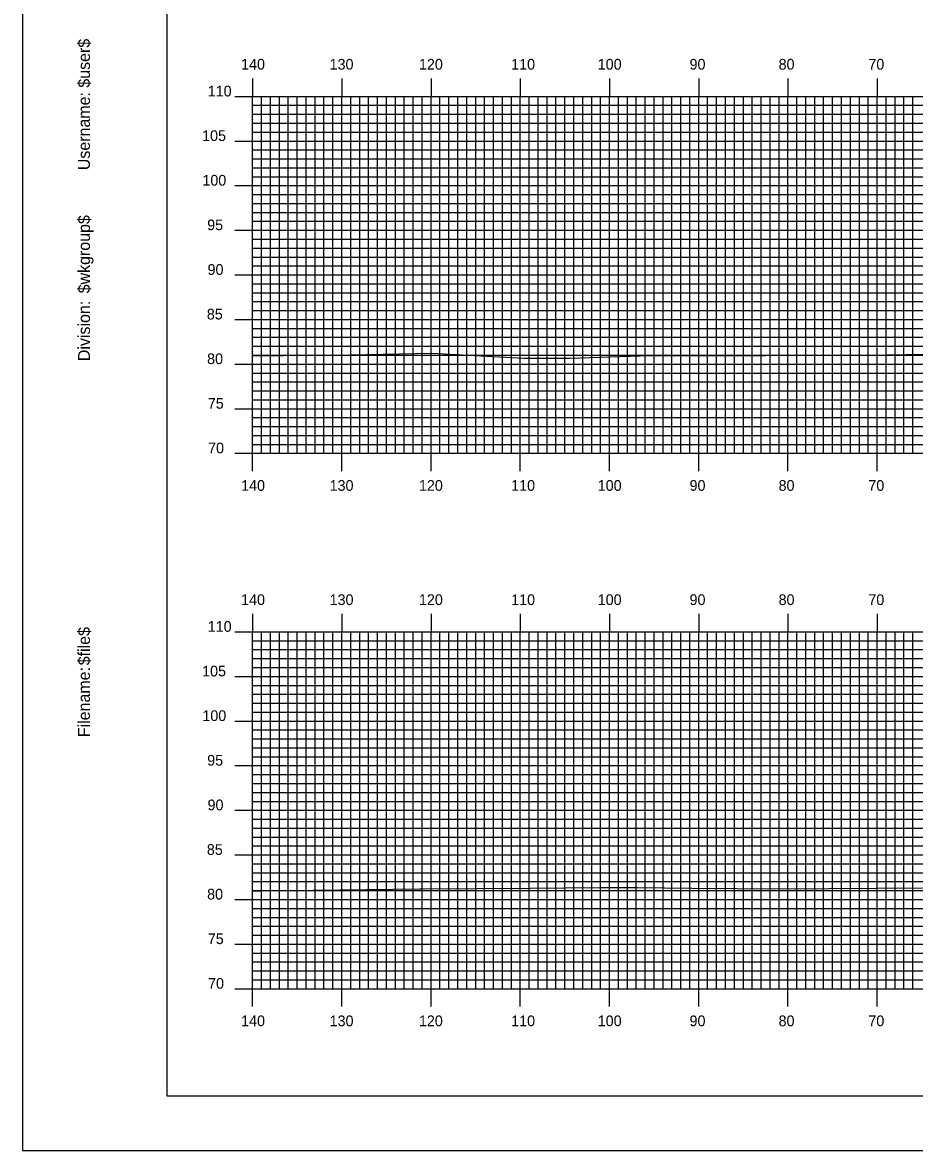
# Model space of a CAD drawing. Extents: x 1759036 to 1759380, y 442591 to 442811.
# Drawn here: x 1759036.4 to 1759136.3, y 442590.5 to 442716.9 of the extents above; entities that cross this region are included whole.
import ezdxf

# ---------------------------------------------------------------- set-up
doc = ezdxf.new("R2010")
doc.units = 0
for name, color, linetype in [('BORDER', 7, 'Continuous'), ('H_V ANNOTATION', 7, 'Continuous'), ('MAJOR', 7, 'Continuous'), ('MINOR', 7, 'Continuous'), ('PLOT BOUNDARY', 7, 'Continuous'), ('S_Roadway_Centerline', 7, 'Continuous')]:
    doc.layers.add(name, color=color, linetype=linetype)

msp = doc.modelspace()

# ---------------------------------------------------------------- linework, layer by layer
at = {"layer": 'BORDER'}
msp.add_lwpolyline([(1759052.56, 442596.67), (1759372.56, 442596.67), (1759372.56, 442806.67), (1759052.56, 442806.67)], close=True, dxfattribs=at)
at = {"layer": 'MAJOR'}
for p, q in [((1759062.16, 442710.67), (1759062.16, 442708.67)), ((1759072.16, 442710.67), (1759072.16, 442708.67)), ((1759082.16, 442710.67), (1759082.16, 442708.67)), ((1759092.16, 442710.67), (1759092.16, 442708.67)), ((1759102.16, 442710.67), (1759102.16, 442708.67)), ((1759112.16, 442710.67), (1759112.16, 442708.67)), ((1759122.16, 442710.67), (1759122.16, 442708.67)), ((1759132.16, 442710.67), (1759132.16, 442708.67)), ((1759060.16, 442708.67), (1759062.16, 442708.67)), ((1759062.16, 442708.67), (1759342.16, 442708.67)), ((1759062.16, 442668.67), (1759062.16, 442708.67)), ((1759062.16, 442668.67), (1759062.16, 442708.67)), ((1759062.16, 442708.67), (1759342.16, 442708.67)), ((1759072.16, 442668.67), (1759072.16, 442708.67)), ((1759082.16, 442668.67), (1759082.16, 442708.67)), ((1759092.16, 442668.67), (1759092.16, 442708.67)), ((1759102.16, 442668.67), (1759102.16, 442708.67)), ((1759112.16, 442668.67), (1759112.16, 442708.67)), ((1759122.16, 442668.67), (1759122.16, 442708.67)), ((1759132.16, 442668.67), (1759132.16, 442708.67)), ((1759060.16, 442703.67), (1759062.16, 442703.67)), ((1759062.16, 442703.67), (1759342.16, 442703.67)), ((1759060.16, 442698.67), (1759062.16, 442698.67)), ((1759062.16, 442698.67), (1759342.16, 442698.67)), ((1759060.16, 442693.67), (1759062.16, 442693.67)), ((1759062.16, 442693.67), (1759342.16, 442693.67)), ((1759060.16, 442688.67), (1759062.16, 442688.67)), ((1759062.16, 442688.67), (1759342.16, 442688.67)), ((1759060.16, 442683.67), (1759062.16, 442683.67)), ((1759062.16, 442683.67), (1759342.16, 442683.67)), ((1759060.16, 442678.67), (1759062.16, 442678.67)), ((1759062.16, 442678.67), (1759342.16, 442678.67)), ((1759060.16, 442673.67), (1759062.16, 442673.67)), ((1759062.16, 442673.67), (1759342.16, 442673.67)), ((1759060.16, 442668.67), (1759062.16, 442668.67)), ((1759062.16, 442668.67), (1759342.16, 442668.67)), ((1759062.16, 442668.67), (1759342.16, 442668.67)), ((1759062.16, 442666.66), (1759062.16, 442668.67)), ((1759072.16, 442666.66), (1759072.16, 442668.67)), ((1759082.16, 442666.66), (1759082.16, 442668.67)), ((1759092.16, 442666.66), (1759092.16, 442668.67)), ((1759102.16, 442666.66), (1759102.16, 442668.67)), ((1759112.16, 442666.66), (1759112.16, 442668.67)), ((1759122.16, 442666.66), (1759122.16, 442668.67)), ((1759132.16, 442666.66), (1759132.16, 442668.67)), ((1759062.16, 442650.67), (1759062.16, 442648.67)), ((1759072.16, 442650.67), (1759072.16, 442648.67)), ((1759082.16, 442650.67), (1759082.16, 442648.67)), ((1759092.16, 442650.67), (1759092.16, 442648.67)), ((1759102.16, 442650.67), (1759102.16, 442648.67)), ((1759112.16, 442650.67), (1759112.16, 442648.67)), ((1759122.16, 442650.67), (1759122.16, 442648.67)), ((1759132.16, 442650.67), (1759132.16, 442648.67)), ((1759060.16, 442648.67), (1759062.16, 442648.67)), ((1759062.16, 442648.67), (1759342.16, 442648.67)), ((1759062.16, 442608.67), (1759062.16, 442648.67)), ((1759062.16, 442608.67), (1759062.16, 442648.67)), ((1759062.16, 442648.67), (1759342.16, 442648.67)), ((1759072.16, 442608.67), (1759072.16, 442648.67)), ((1759082.16, 442608.67), (1759082.16, 442648.67)), ((1759092.16, 442608.67), (1759092.16, 442648.67)), ((1759102.16, 442608.67), (1759102.16, 442648.67)), ((1759112.16, 442608.67), (1759112.16, 442648.67)), ((1759122.16, 442608.67), (1759122.16, 442648.67)), ((1759132.16, 442608.67), (1759132.16, 442648.67)), ((1759060.16, 442643.67), (1759062.16, 442643.67)), ((1759062.16, 442643.67), (1759342.16, 442643.67)), ((1759060.16, 442638.67), (1759062.16, 442638.67)), ((1759062.16, 442638.67), (1759342.16, 442638.67)), ((1759060.16, 442633.67), (1759062.16, 442633.67)), ((1759062.16, 442633.67), (1759342.16, 442633.67)), ((1759060.16, 442628.67), (1759062.16, 442628.67)), ((1759062.16, 442628.67), (1759342.16, 442628.67)), ((1759060.16, 442623.67), (1759062.16, 442623.67)), ((1759062.16, 442623.67), (1759342.16, 442623.67)), ((1759060.16, 442618.67), (1759062.16, 442618.67)), ((1759062.16, 442618.67), (1759342.16, 442618.67)), ((1759060.16, 442613.67), (1759062.16, 442613.67)), ((1759062.16, 442613.67), (1759342.16, 442613.67)), ((1759060.16, 442608.67), (1759062.16, 442608.67)), ((1759062.16, 442608.67), (1759342.16, 442608.67)), ((1759062.16, 442608.67), (1759342.16, 442608.67)), ((1759062.16, 442606.66), (1759062.16, 442608.67)), ((1759072.16, 442606.66), (1759072.16, 442608.67)), ((1759082.16, 442606.66), (1759082.16, 442608.67)), ((1759092.16, 442606.66), (1759092.16, 442608.67)), ((1759102.16, 442606.66), (1759102.16, 442608.67)), ((1759112.16, 442606.66), (1759112.16, 442608.67)), ((1759122.16, 442606.66), (1759122.16, 442608.67)), ((1759132.16, 442606.66), (1759132.16, 442608.67))]:
    msp.add_line(p, q, dxfattribs=at)
at = {"layer": 'MINOR'}
for p, q in [((1759063.16, 442668.67), (1759063.16, 442708.67)), ((1759064.16, 442668.67), (1759064.16, 442708.67)), ((1759065.16, 442668.67), (1759065.16, 442708.67)), ((1759066.16, 442668.67), (1759066.16, 442708.67)), ((1759067.16, 442668.67), (1759067.16, 442708.67)), ((1759068.16, 442668.67), (1759068.16, 442708.67)), ((1759069.16, 442668.67), (1759069.16, 442708.67)), ((1759070.16, 442668.67), (1759070.16, 442708.67)), ((1759071.16, 442668.67), (1759071.16, 442708.67)), ((1759073.16, 442668.67), (1759073.16, 442708.67)), ((1759074.16, 442668.67), (1759074.16, 442708.67)), ((1759075.16, 442668.67), (1759075.16, 442708.67)), ((1759076.16, 442668.67), (1759076.16, 442708.67)), ((1759077.16, 442668.67), (1759077.16, 442708.67)), ((1759078.16, 442668.67), (1759078.16, 442708.67)), ((1759079.16, 442668.67), (1759079.16, 442708.67)), ((1759080.16, 442668.67), (1759080.16, 442708.67)), ((1759081.16, 442668.67), (1759081.16, 442708.67)), ((1759083.16, 442668.67), (1759083.16, 442708.67)), ((1759084.16, 442668.67), (1759084.16, 442708.67)), ((1759085.16, 442668.67), (1759085.16, 442708.67)), ((1759086.16, 442668.67), (1759086.16, 442708.67)), ((1759087.16, 442668.67), (1759087.16, 442708.67)), ((1759088.16, 442668.67), (1759088.16, 442708.67)), ((1759089.16, 442668.67), (1759089.16, 442708.67)), ((1759090.16, 442668.67), (1759090.16, 442708.67)), ((1759091.16, 442668.67), (1759091.16, 442708.67)), ((1759093.16, 442668.67), (1759093.16, 442708.67)), ((1759094.16, 442668.67), (1759094.16, 442708.67)), ((1759095.16, 442668.67), (1759095.16, 442708.67)), ((1759096.16, 442668.67), (1759096.16, 442708.67)), ((1759097.16, 442668.67), (1759097.16, 442708.67)), ((1759098.16, 442668.67), (1759098.16, 442708.67)), ((1759099.16, 442668.67), (1759099.16, 442708.67)), ((1759100.16, 442668.67), (1759100.16, 442708.67)), ((1759101.16, 442668.67), (1759101.16, 442708.67)), ((1759103.16, 442668.67), (1759103.16, 442708.67)), ((1759104.16, 442668.67), (1759104.16, 442708.67)), ((1759105.16, 442668.67), (1759105.16, 442708.67)), ((1759106.16, 442668.67), (1759106.16, 442708.67)), ((1759107.16, 442668.67), (1759107.16, 442708.67)), ((1759108.16, 442668.67), (1759108.16, 442708.67)), ((1759109.16, 442668.67), (1759109.16, 442708.67)), ((1759110.16, 442668.67), (1759110.16, 442708.67)), ((1759111.16, 442668.67), (1759111.16, 442708.67)), ((1759113.16, 442668.67), (1759113.16, 442708.67)), ((1759114.16, 442668.67), (1759114.16, 442708.67)), ((1759115.16, 442668.67), (1759115.16, 442708.67)), ((1759116.16, 442668.67), (1759116.16, 442708.67)), ((1759117.16, 442668.67), (1759117.16, 442708.67)), ((1759118.16, 442668.67), (1759118.16, 442708.67)), ((1759119.16, 442668.67), (1759119.16, 442708.67)), ((1759120.16, 442668.67), (1759120.16, 442708.67)), ((1759121.16, 442668.67), (1759121.16, 442708.67)), ((1759123.16, 442668.67), (1759123.16, 442708.67)), ((1759124.16, 442668.67), (1759124.16, 442708.67)), ((1759125.16, 442668.67), (1759125.16, 442708.67)), ((1759126.16, 442668.67), (1759126.16, 442708.67)), ((1759127.16, 442668.67), (1759127.16, 442708.67)), ((1759128.16, 442668.67), (1759128.16, 442708.67)), ((1759129.16, 442668.67), (1759129.16, 442708.67)), ((1759130.16, 442668.67), (1759130.16, 442708.67)), ((1759131.16, 442668.67), (1759131.16, 442708.67)), ((1759133.16, 442668.67), (1759133.16, 442708.67)), ((1759134.16, 442668.67), (1759134.16, 442708.67)), ((1759135.16, 442668.67), (1759135.16, 442708.67)), ((1759136.16, 442668.67), (1759136.16, 442708.67)), ((1759062.16, 442707.67), (1759342.16, 442707.67)), ((1759062.16, 442707.67), (1759064.17, 442707.67)), ((1759062.16, 442706.67), (1759342.16, 442706.67)), ((1759062.16, 442706.67), (1759064.17, 442706.67)), ((1759062.16, 442705.67), (1759342.16, 442705.67)), ((1759062.16, 442705.67), (1759064.17, 442705.67)), ((1759062.16, 442704.67), (1759342.16, 442704.67)), ((1759062.16, 442704.67), (1759064.17, 442704.67)), ((1759062.16, 442702.67), (1759342.16, 442702.67)), ((1759062.16, 442702.67), (1759064.17, 442702.67)), ((1759062.16, 442701.67), (1759342.16, 442701.67)), ((1759062.16, 442701.67), (1759064.17, 442701.67)), ((1759062.16, 442700.67), (1759342.16, 442700.67)), ((1759062.16, 442700.67), (1759064.17, 442700.67)), ((1759062.16, 442699.67), (1759342.16, 442699.67)), ((1759062.16, 442699.67), (1759064.17, 442699.67)), ((1759062.16, 442697.67), (1759342.16, 442697.67)), ((1759062.16, 442697.67), (1759064.17, 442697.67)), ((1759062.16, 442696.67), (1759342.16, 442696.67)), ((1759062.16, 442696.67), (1759064.17, 442696.67)), ((1759062.16, 442695.67), (1759342.16, 442695.67)), ((1759062.16, 442695.67), (1759064.17, 442695.67)), ((1759062.16, 442694.67), (1759342.16, 442694.67)), ((1759062.16, 442694.67), (1759064.17, 442694.67)), ((1759062.16, 442692.67), (1759342.16, 442692.67)), ((1759062.16, 442692.67), (1759064.17, 442692.67)), ((1759062.16, 442691.67), (1759342.16, 442691.67)), ((1759062.16, 442691.67), (1759064.17, 442691.67)), ((1759062.16, 442690.67), (1759342.16, 442690.67)), ((1759062.16, 442690.67), (1759064.17, 442690.67)), ((1759062.16, 442689.67), (1759342.16, 442689.67)), ((1759062.16, 442689.67), (1759064.17, 442689.67)), ((1759062.16, 442687.67), (1759342.16, 442687.67)), ((1759062.16, 442687.67), (1759064.17, 442687.67)), ((1759062.16, 442686.67), (1759342.16, 442686.67)), ((1759062.16, 442686.67), (1759064.17, 442686.67)), ((1759062.16, 442685.67), (1759342.16, 442685.67)), ((1759062.16, 442685.67), (1759064.17, 442685.67)), ((1759062.16, 442684.67), (1759342.16, 442684.67)), ((1759062.16, 442684.67), (1759064.17, 442684.67)), ((1759062.16, 442682.67), (1759342.16, 442682.67)), ((1759062.16, 442682.67), (1759064.17, 442682.67)), ((1759062.16, 442681.67), (1759342.16, 442681.67)), ((1759062.16, 442681.67), (1759064.17, 442681.67)), ((1759062.16, 442680.67), (1759342.16, 442680.67)), ((1759062.16, 442680.67), (1759064.17, 442680.67)), ((1759062.16, 442679.67), (1759342.16, 442679.67)), ((1759062.16, 442679.67), (1759064.17, 442679.67)), ((1759062.16, 442677.67), (1759342.16, 442677.67)), ((1759062.16, 442677.67), (1759064.17, 442677.67)), ((1759062.16, 442676.67), (1759342.16, 442676.67)), ((1759062.16, 442676.67), (1759064.17, 442676.67)), ((1759062.16, 442675.67), (1759342.16, 442675.67)), ((1759062.16, 442675.67), (1759064.17, 442675.67)), ((1759062.16, 442674.67), (1759342.16, 442674.67)), ((1759062.16, 442674.67), (1759064.17, 442674.67)), ((1759062.16, 442672.67), (1759342.16, 442672.67)), ((1759062.16, 442672.67), (1759064.17, 442672.67)), ((1759062.16, 442671.67), (1759342.16, 442671.67)), ((1759062.16, 442671.67), (1759064.17, 442671.67)), ((1759062.16, 442670.67), (1759342.16, 442670.67)), ((1759062.16, 442670.67), (1759064.17, 442670.67)), ((1759062.16, 442669.67), (1759342.16, 442669.67)), ((1759062.16, 442669.67), (1759064.17, 442669.67)), ((1759063.16, 442608.67), (1759063.16, 442648.67)), ((1759064.16, 442608.67), (1759064.16, 442648.67)), ((1759065.16, 442608.67), (1759065.16, 442648.67)), ((1759066.16, 442608.67), (1759066.16, 442648.67)), ((1759067.16, 442608.67), (1759067.16, 442648.67)), ((1759068.16, 442608.67), (1759068.16, 442648.67)), ((1759069.16, 442608.67), (1759069.16, 442648.67)), ((1759070.16, 442608.67), (1759070.16, 442648.67)), ((1759071.16, 442608.67), (1759071.16, 442648.67)), ((1759073.16, 442608.67), (1759073.16, 442648.67)), ((1759074.16, 442608.67), (1759074.16, 442648.67)), ((1759075.16, 442608.67), (1759075.16, 442648.67)), ((1759076.16, 442608.67), (1759076.16, 442648.67)), ((1759077.16, 442608.67), (1759077.16, 442648.67)), ((1759078.16, 442608.67), (1759078.16, 442648.67)), ((1759079.16, 442608.67), (1759079.16, 442648.67)), ((1759080.16, 442608.67), (1759080.16, 442648.67)), ((1759081.16, 442608.67), (1759081.16, 442648.67)), ((1759083.16, 442608.67), (1759083.16, 442648.67)), ((1759084.16, 442608.67), (1759084.16, 442648.67)), ((1759085.16, 442608.67), (1759085.16, 442648.67)), ((1759086.16, 442608.67), (1759086.16, 442648.67)), ((1759087.16, 442608.67), (1759087.16, 442648.67)), ((1759088.16, 442608.67), (1759088.16, 442648.67)), ((1759089.16, 442608.67), (1759089.16, 442648.67)), ((1759090.16, 442608.67), (1759090.16, 442648.67)), ((1759091.16, 442608.67), (1759091.16, 442648.67)), ((1759093.16, 442608.67), (1759093.16, 442648.67)), ((1759094.16, 442608.67), (1759094.16, 442648.67)), ((1759095.16, 442608.67), (1759095.16, 442648.67)), ((1759096.16, 442608.67), (1759096.16, 442648.67)), ((1759097.16, 442608.67), (1759097.16, 442648.67)), ((1759098.16, 442608.67), (1759098.16, 442648.67)), ((1759099.16, 442608.67), (1759099.16, 442648.67)), ((1759100.16, 442608.67), (1759100.16, 442648.67)), ((1759101.16, 442608.67), (1759101.16, 442648.67)), ((1759103.16, 442608.67), (1759103.16, 442648.67)), ((1759104.16, 442608.67), (1759104.16, 442648.67)), ((1759105.16, 442608.67), (1759105.16, 442648.67)), ((1759106.16, 442608.67), (1759106.16, 442648.67)), ((1759107.16, 442608.67), (1759107.16, 442648.67)), ((1759108.16, 442608.67), (1759108.16, 442648.67)), ((1759109.16, 442608.67), (1759109.16, 442648.67)), ((1759110.16, 442608.67), (1759110.16, 442648.67)), ((1759111.16, 442608.67), (1759111.16, 442648.67)), ((1759113.16, 442608.67), (1759113.16, 442648.67)), ((1759114.16, 442608.67), (1759114.16, 442648.67)), ((1759115.16, 442608.67), (1759115.16, 442648.67)), ((1759116.16, 442608.67), (1759116.16, 442648.67)), ((1759117.16, 442608.67), (1759117.16, 442648.67)), ((1759118.16, 442608.67), (1759118.16, 442648.67)), ((1759119.16, 442608.67), (1759119.16, 442648.67)), ((1759120.16, 442608.67), (1759120.16, 442648.67)), ((1759121.16, 442608.67), (1759121.16, 442648.67)), ((1759123.16, 442608.67), (1759123.16, 442648.67)), ((1759124.16, 442608.67), (1759124.16, 442648.67)), ((1759125.16, 442608.67), (1759125.16, 442648.67)), ((1759126.16, 442608.67), (1759126.16, 442648.67)), ((1759127.16, 442608.67), (1759127.16, 442648.67)), ((1759128.16, 442608.67), (1759128.16, 442648.67)), ((1759129.16, 442608.67), (1759129.16, 442648.67)), ((1759130.16, 442608.67), (1759130.16, 442648.67)), ((1759131.16, 442608.67), (1759131.16, 442648.67)), ((1759133.16, 442608.67), (1759133.16, 442648.67)), ((1759134.16, 442608.67), (1759134.16, 442648.67)), ((1759135.16, 442608.67), (1759135.16, 442648.67)), ((1759136.16, 442608.67), (1759136.16, 442648.67)), ((1759062.16, 442647.67), (1759342.16, 442647.67)), ((1759062.16, 442647.67), (1759064.17, 442647.67)), ((1759062.16, 442646.67), (1759342.16, 442646.67)), ((1759062.16, 442646.67), (1759064.17, 442646.67)), ((1759062.16, 442645.67), (1759342.16, 442645.67)), ((1759062.16, 442645.67), (1759064.17, 442645.67)), ((1759062.16, 442644.67), (1759342.16, 442644.67)), ((1759062.16, 442644.67), (1759064.17, 442644.67)), ((1759062.16, 442642.67), (1759342.16, 442642.67)), ((1759062.16, 442642.67), (1759064.17, 442642.67)), ((1759062.16, 442641.67), (1759342.16, 442641.67)), ((1759062.16, 442641.67), (1759064.17, 442641.67)), ((1759062.16, 442640.67), (1759342.16, 442640.67)), ((1759062.16, 442640.67), (1759064.17, 442640.67)), ((1759062.16, 442639.67), (1759342.16, 442639.67)), ((1759062.16, 442639.67), (1759064.17, 442639.67)), ((1759062.16, 442637.67), (1759342.16, 442637.67)), ((1759062.16, 442637.67), (1759064.17, 442637.67)), ((1759062.16, 442636.67), (1759342.16, 442636.67)), ((1759062.16, 442636.67), (1759064.17, 442636.67)), ((1759062.16, 442635.67), (1759342.16, 442635.67)), ((1759062.16, 442635.67), (1759064.17, 442635.67)), ((1759062.16, 442634.67), (1759342.16, 442634.67)), ((1759062.16, 442634.67), (1759064.17, 442634.67)), ((1759062.16, 442632.67), (1759342.16, 442632.67)), ((1759062.16, 442632.67), (1759064.17, 442632.67)), ((1759062.16, 442631.67), (1759342.16, 442631.67)), ((1759062.16, 442631.67), (1759064.17, 442631.67)), ((1759062.16, 442630.67), (1759342.16, 442630.67)), ((1759062.16, 442630.67), (1759064.17, 442630.67)), ((1759062.16, 442629.67), (1759342.16, 442629.67)), ((1759062.16, 442629.67), (1759064.17, 442629.67)), ((1759062.16, 442627.67), (1759342.16, 442627.67)), ((1759062.16, 442627.67), (1759064.17, 442627.67)), ((1759062.16, 442626.67), (1759342.16, 442626.67)), ((1759062.16, 442626.67), (1759064.17, 442626.67)), ((1759062.16, 442625.67), (1759342.16, 442625.67)), ((1759062.16, 442625.67), (1759064.17, 442625.67)), ((1759062.16, 442624.67), (1759342.16, 442624.67)), ((1759062.16, 442624.67), (1759064.17, 442624.67)), ((1759062.16, 442622.67), (1759342.16, 442622.67)), ((1759062.16, 442622.67), (1759064.17, 442622.67)), ((1759062.16, 442621.67), (1759342.16, 442621.67)), ((1759062.16, 442621.67), (1759064.17, 442621.67)), ((1759062.16, 442620.67), (1759342.16, 442620.67)), ((1759062.16, 442620.67), (1759064.17, 442620.67)), ((1759062.16, 442619.67), (1759342.16, 442619.67)), ((1759062.16, 442619.67), (1759064.17, 442619.67)), ((1759062.16, 442617.67), (1759342.16, 442617.67)), ((1759062.16, 442617.67), (1759064.17, 442617.67)), ((1759062.16, 442616.67), (1759342.16, 442616.67)), ((1759062.16, 442616.67), (1759064.17, 442616.67)), ((1759062.16, 442615.67), (1759342.16, 442615.67)), ((1759062.16, 442615.67), (1759064.17, 442615.67)), ((1759062.16, 442614.67), (1759342.16, 442614.67)), ((1759062.16, 442614.67), (1759064.17, 442614.67)), ((1759062.16, 442612.67), (1759342.16, 442612.67)), ((1759062.16, 442612.67), (1759064.17, 442612.67)), ((1759062.16, 442611.67), (1759342.16, 442611.67)), ((1759062.16, 442611.67), (1759064.17, 442611.67)), ((1759062.16, 442610.67), (1759342.16, 442610.67)), ((1759062.16, 442610.67), (1759064.17, 442610.67)), ((1759062.16, 442609.67), (1759342.16, 442609.67)), ((1759062.16, 442609.67), (1759064.17, 442609.67))]:
    msp.add_line(p, q, dxfattribs=at)
at = {"layer": 'PLOT BOUNDARY'}
msp.add_lwpolyline([(1759036.37, 442590.55), (1759376.37, 442590.55), (1759376.37, 442810.55), (1759036.37, 442810.55)], close=True, dxfattribs=at)
at = {"layer": 'S_Roadway_Centerline'}
for points in [[(1759062.16, 442679.65), (1759065.62, 442679.65), (1759073.13, 442679.7), (1759082.26, 442679.88), (1759092.59, 442679.35), (1759097.73, 442679.35), (1759106.71, 442679.64), (1759112.82, 442679.59), (1759126.49, 442679.67), (1759130.49, 442679.66), (1759133.22, 442679.71), (1759141.87, 442679.84), (1759152.59, 442679.78), (1759153.87, 442679.8), (1759155.98, 442679.79), (1759169.27, 442680.13), (1759190.2, 442680.24), (1759194.89, 442680.1), (1759196.6, 442680.09), (1759204.26, 442680.01), (1759224.65, 442679.73), (1759232.15, 442679.87), (1759243.01, 442680.13)], [(1759062.16, 442619.65), (1759063.02, 442619.65), (1759080.85, 442619.86), (1759081.08, 442619.87), (1759081.22, 442619.87), (1759093.32, 442619.94), (1759101.2, 442620.02), (1759105.25, 442620.02), (1759111.37, 442619.93), (1759121.52, 442619.88), (1759137.23, 442619.98)]]:
    msp.add_lwpolyline(points, dxfattribs=at)

# ---------------------------------------------------------------- texts
at = {"layer": 'BORDER'}
for s, p in [('$user$', (1759043.93, 442709.65)), ('$user$', (1759043.93, 442709.65)), ('Username:', (1759043.93, 442700.4)), ('Username:', (1759043.93, 442700.4)), ('$wkgroup$', (1759043.93, 442686.6)), ('$wkgroup$', (1759043.93, 442686.6)), ('Division:', (1759043.93, 442679)), ('Division:', (1759043.93, 442679)), ('$file$', (1759043.93, 442644.92)), ('$file$', (1759043.93, 442644.92)), ('Filename:', (1759043.93, 442636.86)), ('Filename:', (1759043.93, 442636.86))]:
    msp.add_text(s, height=1.339, rotation=90, dxfattribs=at).set_placement(p)
at = {"layer": 'H_V ANNOTATION'}
for s, p in [('140', (1759060.87, 442711.67)), ('130', (1759070.79, 442711.67)), ('120', (1759080.8, 442711.67)), ('110', (1759091.14, 442711.67)), ('100', (1759100.84, 442711.67)), ('90', (1759111.13, 442711.67)), ('80', (1759121.11, 442711.67)), ('70', (1759131.17, 442711.67)), ('110', (1759057.13, 442708.67)), ('105', (1759056.5, 442703.67)), ('100', (1759056.53, 442698.67)), ('95', (1759057.07, 442693.67)), ('90', (1759057.11, 442688.67)), ('85', (1759057.03, 442683.67)), ('80', (1759057.06, 442678.67)), ('75', (1759057.14, 442673.67)), ('70', (1759057.17, 442668.67)), ('140', (1759060.87, 442664.47)), ('130', (1759070.79, 442664.47)), ('120', (1759080.8, 442664.47)), ('110', (1759091.14, 442664.47)), ('100', (1759100.84, 442664.47)), ('90', (1759111.13, 442664.47)), ('80', (1759121.11, 442664.47)), ('70', (1759131.17, 442664.47)), ('140', (1759060.87, 442651.67)), ('130', (1759070.79, 442651.67)), ('120', (1759080.8, 442651.67)), ('110', (1759091.14, 442651.67)), ('100', (1759100.84, 442651.67)), ('90', (1759111.13, 442651.67)), ('80', (1759121.11, 442651.67)), ('70', (1759131.17, 442651.67)), ('110', (1759057.13, 442648.67)), ('105', (1759056.5, 442643.67)), ('100', (1759056.53, 442638.67)), ('95', (1759057.07, 442633.67)), ('90', (1759057.11, 442628.67)), ('85', (1759057.03, 442623.67)), ('80', (1759057.06, 442618.67)), ('75', (1759057.14, 442613.67)), ('70', (1759057.17, 442608.67)), ('140', (1759060.87, 442604.47)), ('130', (1759070.79, 442604.47)), ('120', (1759080.8, 442604.47)), ('110', (1759091.14, 442604.47)), ('100', (1759100.84, 442604.47)), ('90', (1759111.13, 442604.47)), ('80', (1759121.11, 442604.47)), ('70', (1759131.17, 442604.47))]:
    msp.add_text(s, height=1.2, dxfattribs=at).set_placement(p)
at = {"layer": 'MAJOR'}
for p in [(1759062.15, 442668.67), (1759062.15, 442608.67)]:
    msp.add_text('-', height=0.012, dxfattribs=at).set_placement(p)

doc.saveas('drawing.dxf')
